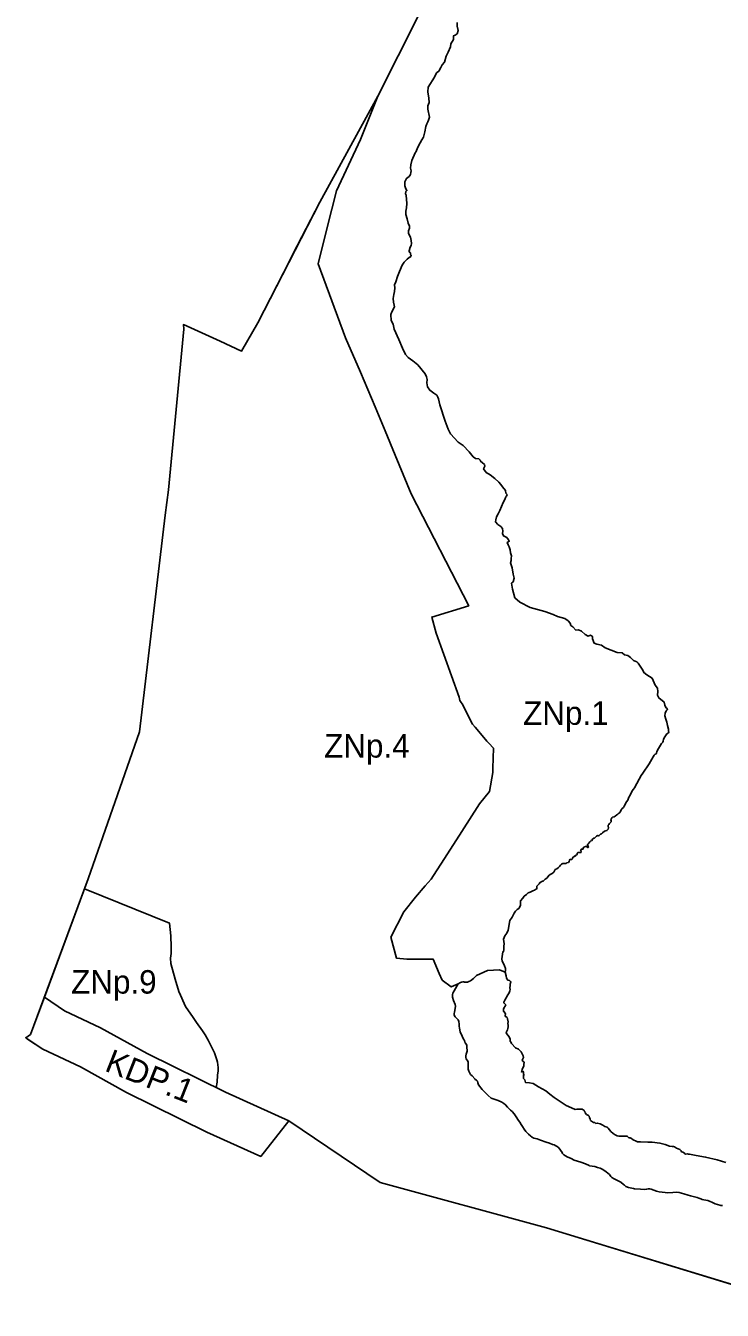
# Model space of a CAD drawing. Extents: x 7421614 to 7422630, y 5544623 to 5545754.
# Drawn here: x 7421614 to 7421911, y 5544623 to 5545171 of the extents above; entities that cross this region are included whole.
import ezdxf

# ---------------------------------------------------------------- set-up
doc = ezdxf.new("R2010")
doc.units = 0
for name, color, linetype in [('LIN_Granica Planu', 7, 'Continuous'), ('LIN_Linia Zabudowy Nieprzekraczalna', 7, 'Continuous'), ('LIN_Linie Rozgraniczajace', 7, 'Continuous'), ('TXT_Oznaczenia Przeznaczenia', 7, 'Continuous')]:
    doc.layers.add(name, color=color, linetype=linetype)

msp = doc.modelspace()

# ---------------------------------------------------------------- linework, layer by layer
at = {"layer": 'LIN_Granica Planu'}
for p, q in [((7421621.05, 5544734.64), (7421613.8, 5544739.54)), ((7421637.08, 5544727.06), (7421621.05, 5544734.64)), ((7421725.94, 5544704.1), (7421713.88, 5544688.95)), ((7421764.74, 5544677.85), (7421725.94, 5544704.1)), ((7421835.68, 5544658.51), (7421764.74, 5544677.85)), ((7421948.36, 5544624.06), (7421835.68, 5544658.51))]:
    msp.add_line(p, q, dxfattribs=at)
for points in [[(7421613.8, 5544739.54), (7421615.88, 5544740.91), (7421640.38, 5544807.28), (7421662.28, 5544869.93), (7421673.19, 5544962.22), (7421674.61, 5544973.03), (7421681.17, 5545041.58), (7421681, 5545043.46), (7421696.65, 5545036.45), (7421705.74, 5545032.15), (7421712.63, 5545044.28), (7421739.11, 5545095.71), (7421763.82, 5545140.89), (7421781.09, 5545175.2)], [(7421713.88, 5544688.95), (7421690.95, 5544699.32), (7421656.77, 5544716.17), (7421637.08, 5544727.06)]]:
    msp.add_lwpolyline(points, dxfattribs=at)
at = {"layer": 'LIN_Linia Zabudowy Nieprzekraczalna'}
msp.add_lwpolyline([(7421694.96, 5544718.27), (7421695.33, 5544720.54), (7421695.47, 5544723.62), (7421695.71, 5544725.38), (7421695.79, 5544726.77), (7421695.47, 5544729.16), (7421695.18, 5544730.05), (7421694.16, 5544733.11), (7421691.52, 5544738.5), (7421690.19, 5544740.75), (7421689.06, 5544742.4), (7421686.57, 5544746.03), (7421685.14, 5544748.12), (7421681.92, 5544752.83), (7421681.35, 5544754.08), (7421679.75, 5544757.61), (7421679.08, 5544759.28), (7421677.48, 5544764.54), (7421675.68, 5544771.18), (7421675.5, 5544773.45), (7421675.7, 5544775.38), (7421675.8, 5544778.29), (7421675.58, 5544783), (7421675.1, 5544788.34), (7421638.78, 5544802.94)], dxfattribs=at)
at = {"layer": 'LIN_Linie Rozgraniczajace'}
for points in [[(7421800.19, 5545340.6), (7421796.3, 5545327.14), (7421796.14, 5545311.14), (7421795.22, 5545291.42), (7421798.07, 5545252.3), (7421796.41, 5545215.4), (7421791.36, 5545199.07), (7421781.09, 5545175.2), (7421763.82, 5545140.89)], [(7421797.57, 5545172.2), (7421797.58, 5545170.62), (7421797.97, 5545168.8), (7421797.61, 5545167.4), (7421796.74, 5545166.78), (7421795.99, 5545166.47), (7421796.01, 5545164.99), (7421794.89, 5545163.11), (7421794.76, 5545161.78), (7421793.76, 5545159.62), (7421792.86, 5545157.93), (7421792.14, 5545155.38), (7421791.13, 5545154.13), (7421790.6, 5545153.04), (7421789.73, 5545151.5), (7421788.72, 5545150.74), (7421787.99, 5545148.99), (7421785.22, 5545144.59), (7421785.07, 5545142.74), (7421785.49, 5545139.94), (7421785.72, 5545138.06), (7421785.13, 5545136.75), (7421785.14, 5545135.25), (7421785.73, 5545131.82), (7421785.42, 5545130.53), (7421785.04, 5545129.94), (7421784.68, 5545128.97), (7421784.24, 5545127.85), (7421783.81, 5545125.63), (7421783.24, 5545123.3), (7421782.51, 5545122.19), (7421781.78, 5545121), (7421780.73, 5545118.86), (7421780.09, 5545117.27), (7421779.74, 5545116.62), (7421778.22, 5545113.44), (7421777.85, 5545111.49), (7421777.71, 5545110.14), (7421778.01, 5545109.04), (7421777.81, 5545108.24), (7421777.67, 5545107.37), (7421777.1, 5545106.52), (7421775.93, 5545105.79), (7421775.24, 5545104.38), (7421775.26, 5545102.62), (7421775.69, 5545101.35), (7421776.2, 5545100.57), (7421775.74, 5545100.15), (7421775.56, 5545099.19), (7421775.8, 5545098.57), (7421776.19, 5545095.07), (7421776.01, 5545093.28), (7421775.77, 5545091.75), (7421775.74, 5545090.35), (7421776.28, 5545088.53), (7421776.72, 5545086.74), (7421777.34, 5545085.43), (7421777.23, 5545084.5), (7421776.9, 5545083.44), (7421776.87, 5545082.33), (7421777.64, 5545080.69), (7421778.05, 5545079.33), (7421778.18, 5545077.96), (7421777.94, 5545077.15), (7421777.5, 5545076.42), (7421777.07, 5545074.97), (7421777.2, 5545074.47), (7421777.72, 5545074.04), (7421777.73, 5545073.38), (7421778.03, 5545073.04), (7421777.72, 5545072.29), (7421777.18, 5545072.11), (7421776.25, 5545071.32), (7421775.03, 5545070.13), (7421774.17, 5545068.84), (7421772.97, 5545066.13), (7421772.2, 5545063.99), (7421771.46, 5545061.7), (7421770.88, 5545060.39), (7421770.98, 5545059.07), (7421770.92, 5545057.59), (7421770.58, 5545056.35), (7421770.3, 5545054.52), (7421770.39, 5545053.04), (7421770.8, 5545051.79), (7421770.82, 5545051.04), (7421769.79, 5545048.94), (7421769.33, 5545047.79), (7421769.46, 5545045.21), (7421770.28, 5545043.58), (7421770.78, 5545041.57), (7421772.74, 5545037.18), (7421774.23, 5545033.4), (7421775.6, 5545030.69), (7421776.73, 5545029.38), (7421778.66, 5545028.07), (7421780.84, 5545026.25), (7421783.92, 5545022.48), (7421784.57, 5545021.15), (7421784.79, 5545020.04), (7421784.59, 5545018.66), (7421785, 5545016.97), (7421785.98, 5545015.46), (7421787.71, 5545014.27), (7421788.87, 5545013.33), (7421789.36, 5545012.52), (7421789.6, 5545011.87), (7421790.26, 5545009.26), (7421792.53, 5545002.27), (7421793.76, 5544998.95), (7421794.69, 5544996.94), (7421798.03, 5544993.37), (7421800.19, 5544991.97), (7421802.73, 5544989.18), (7421804.4, 5544987.17), (7421805.42, 5544986.44), (7421806.8, 5544986.23), (7421807.44, 5544985.72), (7421807.71, 5544985.07), (7421808.29, 5544984.72), (7421809.25, 5544983.81), (7421809.42, 5544983.17), (7421809.14, 5544982.51), (7421808.86, 5544981.99), (7421809.93, 5544980.49), (7421811.6, 5544979.46), (7421813.65, 5544977.81), (7421815.32, 5544976.3), (7421816.2, 5544975.28), (7421816.86, 5544974.31), (7421818.22, 5544972.71), (7421818.36, 5544971.6), (7421818.85, 5544971.09), (7421818.66, 5544970.4), (7421818.25, 5544969.99), (7421817.83, 5544968.9), (7421817.14, 5544967.65), (7421815.77, 5544964.22), (7421815.01, 5544962.87), (7421814.36, 5544961.57), (7421814.07, 5544960.31), (7421813.92, 5544959.34), (7421814.96, 5544958.2), (7421816.17, 5544957.37), (7421816.83, 5544956.55), (7421817.04, 5544955.48), (7421816.95, 5544954.49), (7421817.36, 5544953.38), (7421818.69, 5544952.71), (7421819.41, 5544951.73), (7421819.73, 5544951.09), (7421818.94, 5544950.63), (7421819.27, 5544949.65), (7421819.77, 5544948.74), (7421820.19, 5544947.42), (7421820.31, 5544946.17), (7421820.69, 5544944.85), (7421820.52, 5544943.75), (7421820.56, 5544942.93), (7421820.31, 5544941.93), (7421821.07, 5544939.74), (7421821.45, 5544937.09), (7421821.87, 5544935.46), (7421821.37, 5544933.83), (7421820.74, 5544933.24), (7421821.15, 5544930.72), (7421822.12, 5544927.07), (7421824.29, 5544925.19), (7421828.72, 5544922.92), (7421834.91, 5544921.25), (7421838.42, 5544919.89), (7421840.3, 5544919.09), (7421843.38, 5544918.13), (7421844.81, 5544917.27), (7421845.64, 5544916.18), (7421845.97, 5544915.27), (7421846.84, 5544914.62), (7421848.09, 5544913.28), (7421849.31, 5544913.34), (7421850.54, 5544912.79), (7421852.1, 5544911.32), (7421853.36, 5544910.66), (7421854.39, 5544911.06), (7421855.2, 5544910.59), (7421855.18, 5544909.59), (7421855.93, 5544907.71), (7421857.12, 5544907.26), (7421859.1, 5544906.79), (7421860.66, 5544905.65), (7421865.75, 5544903.72), (7421867.87, 5544903.54), (7421868.8, 5544902.78), (7421870.27, 5544902.4), (7421871.46, 5544901.61), (7421872.65, 5544900.32), (7421874.08, 5544899.75), (7421874.71, 5544899.17), (7421876.6, 5544896.11), (7421877.1, 5544895.12), (7421878.36, 5544894.17), (7421880.68, 5544892.75), (7421881.97, 5544889.75), (7421882.94, 5544888.47), (7421883.06, 5544887.07), (7421882.88, 5544885.53), (7421883.47, 5544884.32), (7421885.7, 5544882.57), (7421886.01, 5544881.28), (7421886.45, 5544880.26), (7421887.11, 5544879.73), (7421887.07, 5544879.25), (7421886.62, 5544878.79), (7421886.16, 5544877.89), (7421886.07, 5544876.65), (7421886.52, 5544875.36), (7421886.86, 5544874.02), (7421887.11, 5544872.55), (7421887.54, 5544870.99), (7421887.65, 5544870.22), (7421887.69, 5544869.9), (7421887.53, 5544869.5), (7421887.17, 5544869.12), (7421886.91, 5544869.01), (7421886.04, 5544867.7), (7421885.45, 5544866.72), (7421885.29, 5544865.95), (7421885.16, 5544865.53), (7421884.68, 5544864.99), (7421883.28, 5544862.83), (7421882.69, 5544861.49), (7421882.52, 5544860.8), (7421882.32, 5544860.53), (7421881.86, 5544860.4), (7421881.5, 5544860.02), (7421881.06, 5544859.24), (7421879.3, 5544856.28), (7421876.69, 5544852.34), (7421875.99, 5544851.25), (7421875.16, 5544849.69), (7421873.1, 5544846.07), (7421872.63, 5544845.48), (7421872.18, 5544844.72), (7421871.13, 5544842.57), (7421870.69, 5544842.05), (7421870.24, 5544840.77), (7421869.72, 5544840.03), (7421868.73, 5544838.23), (7421868.38, 5544837.68), (7421867.86, 5544837.21), (7421867.45, 5544836.6), (7421867.13, 5544835.97), (7421866.76, 5544835.35), (7421866.46, 5544835.18), (7421866.04, 5544834.77), (7421865.59, 5544834.53), (7421864.89, 5544833.98), (7421864.44, 5544833.72), (7421863.73, 5544833.48), (7421863.47, 5544833.19), (7421863.05, 5544832.35), (7421863.19, 5544831.98), (7421863.18, 5544831.57), (7421862.91, 5544831.19), (7421862.42, 5544830.8), (7421862.25, 5544830.46), (7421861.9, 5544830.08), (7421861.85, 5544829.72), (7421862.03, 5544829.03), (7421861.88, 5544828.47), (7421861.62, 5544828.07), (7421861.32, 5544827.79), (7421860.33, 5544827.6), (7421859.49, 5544826.79), (7421859.09, 5544826.48), (7421858.63, 5544826.3), (7421858.03, 5544825.69), (7421857.67, 5544825.52), (7421857.37, 5544825.69), (7421856.92, 5544825.44), (7421856.04, 5544824.62), (7421855.79, 5544824.52), (7421855.28, 5544824.2), (7421855.07, 5544823.92), (7421855.09, 5544823.66), (7421854.92, 5544823.5), (7421854.61, 5544823.6), (7421854.11, 5544823.04), (7421853.65, 5544822.43), (7421853.19, 5544822.02), (7421853.14, 5544821.66), (7421853.22, 5544821.4), (7421853.4, 5544821.19), (7421853.45, 5544820.91), (7421853.32, 5544820.66), (7421853.15, 5544820.63), (7421852.91, 5544820.68), (7421852.74, 5544820.93), (7421852.65, 5544821.2), (7421852.29, 5544820.96), (7421851.6, 5544820.74), (7421851.28, 5544820.31), (7421851.12, 5544819.86), (7421850.46, 5544819.96), (7421850.18, 5544819.63), (7421850.2, 5544819.34), (7421850.46, 5544819.04), (7421850.29, 5544818.43), (7421849.99, 5544818.42), (7421849.49, 5544818.49), (7421849.09, 5544818.44), (7421848.73, 5544818.16), (7421848.7, 5544817.8), (7421848.52, 5544817.49), (7421848.19, 5544817.28), (7421847.86, 5544816.94), (7421847.55, 5544816.91), (7421846.73, 5544816.25), (7421846.65, 5544815.81), (7421846.38, 5544815.47), (7421846.07, 5544815.42), (7421845.77, 5544815.59), (7421845.42, 5544815.2), (7421845.24, 5544814.58), (7421844.93, 5544814.21), (7421844.29, 5544814.12), (7421844.01, 5544813.8), (7421842.56, 5544813.74), (7421842.07, 5544813.47), (7421841.63, 5544813.05), (7421841.12, 5544812.47), (7421840.67, 5544811.87), (7421839.98, 5544811.46), (7421839.38, 5544811.22), (7421838.69, 5544810.04), (7421838, 5544809.53), (7421837.42, 5544809.3), (7421836.83, 5544808.76), (7421835.71, 5544807.51), (7421835.03, 5544807.15), (7421834.27, 5544806.18), (7421833.92, 5544806.24), (7421833.33, 5544806.03), (7421832.85, 5544805.61), (7421832.5, 5544805.05), (7421831.54, 5544804.13), (7421831.52, 5544803.23), (7421831.46, 5544802.93), (7421831.09, 5544802.9), (7421830.74, 5544802.55), (7421829.59, 5544801.95), (7421828.65, 5544801.52), (7421827.81, 5544801.21), (7421827.08, 5544800.5), (7421826.12, 5544799.8), (7421825.5, 5544798.97), (7421824.53, 5544797.84), (7421824.51, 5544797.26), (7421824.6, 5544796.49), (7421824.51, 5544795.82), (7421823.78, 5544794.64), (7421823.11, 5544794.24), (7421822.45, 5544793.45), (7421821.87, 5544792.58), (7421820.97, 5544790.89), (7421819.96, 5544789.49), (7421819.32, 5544785.33), (7421818.73, 5544784.11), (7421817.95, 5544783.02), (7421817.38, 5544781.59), (7421817.59, 5544779.53), (7421817.5, 5544778.61), (7421817.47, 5544777.05), (7421817.34, 5544776.25), (7421816.99, 5544776.12), (7421816.56, 5544773.21), (7421816.74, 5544772.17), (7421817.39, 5544770.82), (7421817.78, 5544770.23), (7421818.2, 5544769), (7421818.22, 5544768.21), (7421818.07, 5544767.53)], [(7421763.82, 5545140.89), (7421739.11, 5545095.71), (7421729.49, 5545077.03), (7421723.58, 5545065.56), (7421712.63, 5545044.28), (7421705.74, 5545032.15), (7421696.65, 5545036.45), (7421681, 5545043.46), (7421681.17, 5545041.58), (7421674.61, 5544973.03), (7421673.19, 5544962.22), (7421662.28, 5544869.93), (7421640.38, 5544807.28), (7421621.75, 5544756.82)], [(7421797.97, 5544762.54), (7421795.03, 5544761.19), (7421791.23, 5544764.08), (7421789.94, 5544766.85), (7421787.39, 5544772.99), (7421781.23, 5544772.97), (7421776.17, 5544772.96), (7421771.74, 5544773.39), (7421769.36, 5544782.43), (7421774.87, 5544793.11), (7421779.81, 5544799.44), (7421784, 5544804.25), (7421786.49, 5544807.1), (7421787.48, 5544808.61), (7421792.25, 5544815.88), (7421799.63, 5544827.4), (7421807.16, 5544839.14), (7421811.31, 5544844.45), (7421812.74, 5544852.62), (7421812.8, 5544854.45), (7421813.09, 5544862.88), (7421811.06, 5544865.03), (7421810.27, 5544865.96), (7421808.99, 5544867.45), (7421805.25, 5544871.83), (7421804.09, 5544873.2), (7421799.71, 5544881.77), (7421799.22, 5544882.36), (7421798.75, 5544883.3), (7421798.45, 5544884.68), (7421788.57, 5544911.96), (7421786.78, 5544918.77), (7421802.5, 5544923.67), (7421777.96, 5544971.36), (7421774.55, 5544979.62), (7421771.15, 5544987.88), (7421766.91, 5544998.17), (7421762.67, 5545008.45), (7421756.34, 5545023.16), (7421750.01, 5545037.87), (7421744.19, 5545053.6), (7421738.37, 5545069.33), (7421742.25, 5545084.9), (7421746.12, 5545100.47), (7421751.29, 5545111.4), (7421756.47, 5545122.32), (7421760.14, 5545131.61), (7421763.82, 5545140.89)], [(7421694.96, 5544718.27), (7421695.33, 5544720.54), (7421695.47, 5544723.62), (7421695.71, 5544725.38), (7421695.79, 5544726.77), (7421695.47, 5544729.16), (7421695.18, 5544730.05), (7421694.16, 5544733.11), (7421691.52, 5544738.5), (7421690.19, 5544740.75), (7421689.06, 5544742.4), (7421686.57, 5544746.03), (7421685.14, 5544748.12), (7421681.92, 5544752.83), (7421681.35, 5544754.08), (7421679.75, 5544757.61), (7421679.08, 5544759.28), (7421677.48, 5544764.54), (7421675.68, 5544771.18), (7421675.5, 5544773.45), (7421675.7, 5544775.38), (7421675.8, 5544778.29), (7421675.58, 5544783), (7421675.1, 5544788.34), (7421638.78, 5544802.94)], [(7421818.07, 5544767.53), (7421815.65, 5544768.44), (7421810.51, 5544768.19), (7421805.86, 5544765.99), (7421804.47, 5544764.81), (7421803.28, 5544763.74), (7421802.56, 5544763.42), (7421801.93, 5544763.21), (7421801.26, 5544763.15), (7421800.77, 5544763.16), (7421800.39, 5544763.3), (7421800, 5544763.3), (7421799.48, 5544763.24), (7421798.99, 5544763.05), (7421797.97, 5544762.54)], [(7421818.07, 5544767.53), (7421818.46, 5544765.94), (7421818.58, 5544764.94), (7421819.14, 5544764.08), (7421819.83, 5544763.9), (7421820.34, 5544763.42), (7421820.47, 5544763.02), (7421820.15, 5544762.45), (7421820.22, 5544761.77), (7421820.08, 5544760.81), (7421820.13, 5544760.08), (7421820.05, 5544759.5), (7421819.75, 5544758.7), (7421819.17, 5544757.76), (7421817.92, 5544755.48), (7421817.51, 5544754.67), (7421817.45, 5544754.33), (7421818.26, 5544753.51), (7421818.05, 5544753.04), (7421817.59, 5544752.34), (7421817.29, 5544751.63), (7421817.34, 5544750.95), (7421817.47, 5544750.58), (7421817.77, 5544750.44), (7421817.86, 5544750.07), (7421818.1, 5544749.73), (7421818.07, 5544748.94), (7421818.18, 5544748.57), (7421818.52, 5544748.38), (7421818.82, 5544748.08), (7421819.02, 5544747.55), (7421819.24, 5544746.23), (7421819.2, 5544745.6), (7421819.32, 5544744.93), (7421819.33, 5544744.17), (7421819.17, 5544743.48), (7421818.95, 5544742.87), (7421818.7, 5544742.25), (7421818.4, 5544741.73), (7421818.62, 5544741.35), (7421819.77, 5544739.87), (7421820.12, 5544738.87), (7421820.12, 5544738.45), (7421820.19, 5544738.07), (7421820.62, 5544737.44), (7421820.77, 5544737.06), (7421822.43, 5544735.18), (7421823.69, 5544734.64), (7421824.9, 5544733.5), (7421825.65, 5544731.79), (7421825.78, 5544731.06), (7421825.3, 5544729.92), (7421825.5, 5544729.57), (7421826.08, 5544729.08), (7421825.92, 5544728.12), (7421825.95, 5544727.49), (7421825.75, 5544726.9), (7421825.37, 5544726.37), (7421825.29, 5544725.95), (7421825.08, 5544725.46), (7421824.98, 5544724.88), (7421825.33, 5544725.25), (7421825.76, 5544725.16), (7421825.88, 5544724.74), (7421825.89, 5544724.17), (7421826.01, 5544723.75), (7421825.8, 5544723.35), (7421825.79, 5544722.75), (7421825.87, 5544722.08), (7421826.35, 5544721.61), (7421826.59, 5544721.01), (7421826.75, 5544720.38), (7421828.33, 5544720.35), (7421830, 5544720), (7421832.17, 5544718.55), (7421835.33, 5544716.87), (7421836.99, 5544715.5), (7421838.94, 5544714.05), (7421844, 5544710.59), (7421846.21, 5544709.61), (7421847.81, 5544708.98), (7421848.6, 5544709.11), (7421849.94, 5544709.14), (7421850.84, 5544709.02), (7421851.22, 5544708.85), (7421851.55, 5544708.59), (7421851.74, 5544708.31), (7421852.02, 5544708.08), (7421852.08, 5544707.5), (7421852.67, 5544706.81), (7421853.54, 5544706.33), (7421853.75, 5544706.11), (7421853.92, 5544705.46), (7421854.21, 5544704.86), (7421854.42, 5544704.25), (7421855.61, 5544703.46), (7421856.22, 5544703.36), (7421856.71, 5544703.01), (7421857.22, 5544703.12), (7421858.48, 5544702.78), (7421859.58, 5544702.32), (7421860.51, 5544701.73), (7421861.42, 5544701.34), (7421861.85, 5544701.02), (7421863.04, 5544699.5), (7421864.03, 5544698.67), (7421864.92, 5544698.13), (7421865.71, 5544697.78), (7421866.48, 5544697.56), (7421868.11, 5544697.6), (7421868.73, 5544697.55), (7421869.59, 5544697.61), (7421870, 5544697.57), (7421870.37, 5544697.15), (7421870.66, 5544696.92), (7421871.25, 5544696.82), (7421871.9, 5544696.51), (7421872.48, 5544696.04), (7421873.79, 5544695.49), (7421874.44, 5544695.15), (7421875.05, 5544695.18), (7421875.69, 5544695.22), (7421878.82, 5544695.08), (7421879.52, 5544694.99), (7421879.99, 5544695.03), (7421880.6, 5544694.99), (7421883.94, 5544694.6), (7421886.23, 5544693.99), (7421888.05, 5544693.36), (7421889.22, 5544693.17), (7421889.7, 5544693.18), (7421890.09, 5544693.02), (7421891.07, 5544692.43), (7421892.38, 5544691.83), (7421892.85, 5544691.53), (7421893, 5544691.25), (7421893.08, 5544690.95), (7421893.71, 5544690.78), (7421894.22, 5544690.49), (7421894.59, 5544690.09), (7421894.85, 5544689.91), (7421895.66, 5544689.97), (7421896.1, 5544689.84), (7421896.56, 5544689.84), (7421899.42, 5544689.29), (7421903.39, 5544688.65), (7421908.35, 5544687.47), (7421911.99, 5544686.34)], [(7421797.97, 5544762.54), (7421795.7, 5544758.55), (7421795.57, 5544757.91), (7421795.6, 5544756.87), (7421796.01, 5544755.45), (7421796.73, 5544753.71), (7421796.88, 5544753.04), (7421796.78, 5544751.91), (7421796.43, 5544750.36), (7421796.3, 5544749.78), (7421796.36, 5544749.2), (7421796.75, 5544748.36), (7421796.95, 5544748.14), (7421797.58, 5544747.6), (7421798.03, 5544747.08), (7421798.25, 5544746.43), (7421798.39, 5544745.29), (7421798.49, 5544744.41), (7421798.54, 5544743.53), (7421798.88, 5544742.08), (7421799.69, 5544740.13), (7421800.34, 5544738.88), (7421800.69, 5544738.4), (7421800.9, 5544737.68), (7421800.93, 5544737.55), (7421801, 5544737.32), (7421801.55, 5544736.6), (7421801.75, 5544736.15), (7421801.75, 5544735.11), (7421801.87, 5544734.31), (7421801.85, 5544733.85), (7421801.47, 5544732.45), (7421801.28, 5544731.74), (7421801.21, 5544731.15), (7421801.48, 5544730.53), (7421802.14, 5544729.59), (7421802.31, 5544729.15), (7421802.32, 5544728.32), (7421802.21, 5544727.42), (7421802.25, 5544726.68), (7421802.27, 5544726.15), (7421802.54, 5544725.3), (7421802.84, 5544724.67), (7421803.29, 5544723.91), (7421803.9, 5544723.27), (7421805.11, 5544721.98), (7421805.3, 5544721.77), (7421805.86, 5544721.38), (7421806.22, 5544720.96), (7421806.36, 5544720.3), (7421806.66, 5544719.4), (7421808.19, 5544717.5), (7421809.59, 5544716), (7421810.81, 5544714.86), (7421812.08, 5544713.78), (7421815.1, 5544712.7), (7421816.54, 5544712.04), (7421817.47, 5544711.54), (7421818.22, 5544710.95), (7421818.96, 5544709.99), (7421819.38, 5544709.44), (7421820.32, 5544708.63), (7421820.96, 5544708.08), (7421821.82, 5544707.05), (7421822.64, 5544705.79), (7421823.65, 5544704.24), (7421824.25, 5544703.51), (7421824.8, 5544702.52), (7421825.37, 5544701.66), (7421826.08, 5544700.59), (7421826.89, 5544699.59), (7421828.01, 5544698.48), (7421828.95, 5544697.55), (7421829.22, 5544697.28), (7421830.26, 5544696.73), (7421831.63, 5544696.38), (7421833.14, 5544695.8), (7421835.46, 5544695.07), (7421836.93, 5544694.52), (7421838.15, 5544694.06), (7421838.84, 5544693.88), (7421839.66, 5544693.46), (7421840.18, 5544693.18), (7421840.83, 5544692.64), (7421841.59, 5544691.66), (7421842.26, 5544690.61), (7421842.5, 5544690.23), (7421843.08, 5544689.65), (7421843.68, 5544689.25), (7421844.39, 5544688.78), (7421846.13, 5544687.98), (7421847.37, 5544687.41), (7421850.25, 5544686.44), (7421852.3, 5544685.74), (7421853.75, 5544685.08), (7421854, 5544684.97), (7421856.18, 5544684.58), (7421857.37, 5544684.25), (7421858.42, 5544683.86), (7421859.66, 5544683.3), (7421861.1, 5544682.35), (7421862.49, 5544681.17), (7421863.01, 5544680.41), (7421863.24, 5544680.2), (7421863.47, 5544679.99), (7421863.71, 5544679.78), (7421864.21, 5544679.48), (7421866.41, 5544678.41), (7421867.28, 5544677.9), (7421868.38, 5544676.99), (7421868.79, 5544676.65), (7421869.37, 5544676.17), (7421870.5, 5544675.75), (7421872.62, 5544675.25), (7421873.12, 5544675.19), (7421875.63, 5544674.97), (7421877.48, 5544674.8), (7421878.28, 5544674.92), (7421878.91, 5544675.08), (7421879.63, 5544675.16), (7421880.16, 5544675), (7421881.39, 5544674.52), (7421882.46, 5544674.1), (7421883.68, 5544673.87), (7421884.9, 5544673.64), (7421886.14, 5544673.54), (7421887.24, 5544673.45), (7421889.41, 5544673.54), (7421890.82, 5544673.67), (7421892.09, 5544673.58), (7421894.13, 5544673.03), (7421895.93, 5544672.47), (7421896.97, 5544672.14), (7421899.8, 5544671.38), (7421900.57, 5544671.17), (7421901.3, 5544670.85), (7421901.92, 5544670.58), (7421902.59, 5544670.45), (7421904.33, 5544670.19), (7421905.4, 5544669.76), (7421906.05, 5544669.4), (7421907.54, 5544668.73), (7421908.52, 5544668.41), (7421909.43, 5544668.1), (7421909.83, 5544668.08), (7421910.66, 5544668.07)], [(7421725.94, 5544704.1), (7421713.88, 5544688.95), (7421690.95, 5544699.32), (7421656.77, 5544716.17), (7421637.08, 5544727.06), (7421621.05, 5544734.64), (7421615.05, 5544738.69), (7421613.8, 5544739.54), (7421615.88, 5544740.91), (7421621.75, 5544756.82)], [(7421725.94, 5544704.1), (7421698.97, 5544716.29), (7421665.47, 5544732.82), (7421645.65, 5544743.78), (7421630.37, 5544751), (7421621.75, 5544756.82)], [(7421725.94, 5544704.1), (7421764.74, 5544677.85), (7421835.68, 5544658.51), (7421860.75, 5544650.85), (7421948.36, 5544624.06), (7421967.91, 5544623.35), (7421979.89, 5544632.08), (7421999.46, 5544646.33), (7422039.86, 5544675.74)]]:
    msp.add_lwpolyline(points, dxfattribs=at)

# ---------------------------------------------------------------- texts
at = {"layer": 'TXT_Oznaczenia Przeznaczenia'}
for s, p in [('ZNp.1', (7421825.68, 5544872.88)), ('ZNp.4', (7421740.92, 5544858.92)), ('ZNp.9', (7421633.16, 5544758.33))]:
    msp.add_text(s, height=10, dxfattribs=at).set_placement(p)
msp.add_text('KDP.1', height=10, rotation=338.4747, dxfattribs=at).set_placement((7421646.99, 5544725.58))

doc.saveas('drawing.dxf')
